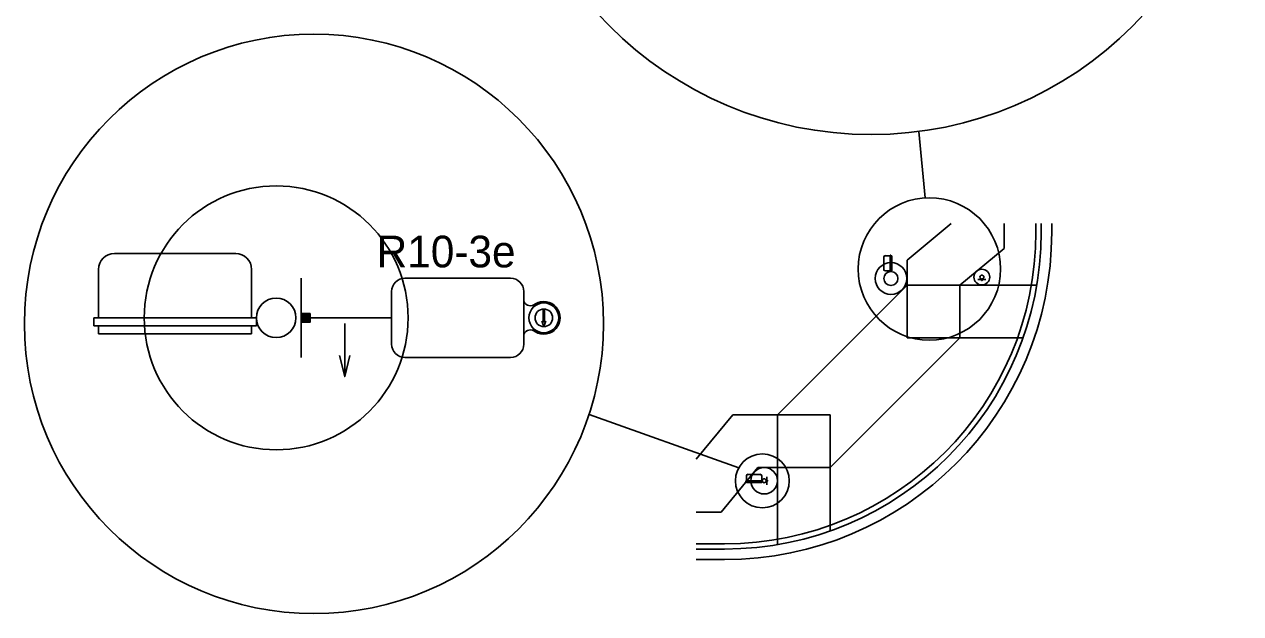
# Model space of a CAD drawing. Extents: x 1369885 to 1370886, y 379976 to 380616.
# Drawn here: x 1370436.8 to 1370609.7, y 380082.1 to 380165.8 of the extents above; entities that cross this region are included whole.
import ezdxf

# ---------------------------------------------------------------- set-up
doc = ezdxf.new("R2010")
doc.units = 0
doc.layers.add('T_Drafting', color=7, linetype='Continuous')

msp = doc.modelspace()

# ---------------------------------------------------------------- linework, layer by layer
at = {"layer": 'T_Drafting'}
for p, q in [((1370564.83, 380141.13), (1370563.93, 380150.57)), ((1370562.24, 380132.29), (1370568.54, 380137.47)), ((1370576.06, 380133.95), (1370576.06, 380137.47)), ((1370580.56, 380136.25), (1370580.56, 380137.47)), ((1370581.31, 380136.25), (1370581.31, 380137.47)), ((1370582.81, 380136.25), (1370582.81, 380137.47)), ((1370449.58, 380133.22), (1370466.83, 380133.22)), ((1370558.93, 380130.97), (1370558.93, 380132.7)), ((1370559.85, 380132.92), (1370559.16, 380132.92)), ((1370559.85, 380130.68), (1370559.85, 380132.99)), ((1370559.96, 380132.99), (1370559.85, 380132.99)), ((1370559.96, 380130.68), (1370559.96, 380132.99)), ((1370560.07, 380132.92), (1370559.96, 380132.92)), ((1370560.07, 380130.75), (1370560.07, 380132.92)), ((1370569.74, 380128.75), (1370576.06, 380133.95)), ((1370447.33, 380124.09), (1370447.33, 380130.97)), ((1370469.08, 380124.09), (1370469.08, 380130.97)), ((1370559.85, 380130.75), (1370559.16, 380130.75)), ((1370559.96, 380130.68), (1370559.85, 380130.68)), ((1370560.07, 380130.75), (1370559.96, 380130.75)), ((1370562.24, 380132.29), (1370562.24, 380121.25)), ((1370476.14, 380129.72), (1370476.14, 380118.47)), ((1370505.89, 380129.72), (1370490.87, 380129.72)), ((1370573.44, 380129.52), (1370572.32, 380129.52)), ((1370572.82, 380129.39), (1370572.82, 380129.52)), ((1370572.82, 380129.39), (1370572.94, 380129.52)), ((1370572.82, 380129.39), (1370572.94, 380129.52)), ((1370572.82, 380129.4), (1370572.94, 380129.52)), ((1370572.82, 380129.4), (1370572.94, 380129.52)), ((1370572.82, 380129.4), (1370572.94, 380129.52)), ((1370572.82, 380129.4), (1370572.94, 380129.52)), ((1370572.82, 380129.4), (1370572.94, 380129.52)), ((1370572.82, 380129.41), (1370572.93, 380129.52)), ((1370572.82, 380129.41), (1370572.93, 380129.52)), ((1370572.82, 380129.41), (1370572.93, 380129.52)), ((1370572.82, 380129.41), (1370572.93, 380129.52)), ((1370572.82, 380129.41), (1370572.92, 380129.52)), ((1370572.82, 380129.42), (1370572.92, 380129.52)), ((1370572.82, 380129.42), (1370572.92, 380129.52)), ((1370572.82, 380129.42), (1370572.92, 380129.52)), ((1370572.82, 380129.42), (1370572.92, 380129.52)), ((1370572.82, 380129.43), (1370572.91, 380129.52)), ((1370572.82, 380129.43), (1370572.91, 380129.52)), ((1370572.82, 380129.43), (1370572.91, 380129.52)), ((1370572.82, 380129.43), (1370572.91, 380129.52)), ((1370572.82, 380129.43), (1370572.91, 380129.52)), ((1370572.82, 380129.44), (1370572.9, 380129.52)), ((1370572.82, 380129.44), (1370572.9, 380129.52)), ((1370572.82, 380129.44), (1370572.9, 380129.52)), ((1370572.82, 380129.44), (1370572.9, 380129.52)), ((1370572.82, 380129.44), (1370572.89, 380129.52)), ((1370572.82, 380129.45), (1370572.89, 380129.52)), ((1370572.82, 380129.45), (1370572.89, 380129.52)), ((1370572.82, 380129.45), (1370572.89, 380129.52)), ((1370572.82, 380129.45), (1370572.89, 380129.52)), ((1370572.82, 380129.45), (1370572.88, 380129.52)), ((1370572.82, 380129.46), (1370572.88, 380129.52)), ((1370572.82, 380129.46), (1370572.88, 380129.52)), ((1370572.82, 380129.46), (1370572.88, 380129.52)), ((1370572.82, 380129.46), (1370572.88, 380129.52)), ((1370572.82, 380129.47), (1370572.87, 380129.52)), ((1370572.82, 380129.47), (1370572.87, 380129.52)), ((1370572.82, 380129.47), (1370572.87, 380129.52)), ((1370572.82, 380129.47), (1370572.87, 380129.52)), ((1370572.82, 380129.47), (1370572.87, 380129.52)), ((1370572.82, 380129.48), (1370572.86, 380129.52)), ((1370572.82, 380129.48), (1370572.86, 380129.52)), ((1370572.82, 380129.48), (1370572.86, 380129.52)), ((1370572.82, 380129.48), (1370572.86, 380129.52)), ((1370572.82, 380129.48), (1370572.85, 380129.52)), ((1370572.82, 380129.49), (1370572.85, 380129.52)), ((1370572.82, 380129.49), (1370572.85, 380129.52)), ((1370572.82, 380129.49), (1370572.85, 380129.52)), ((1370572.82, 380129.49), (1370572.85, 380129.52)), ((1370572.82, 380129.5), (1370572.84, 380129.52)), ((1370572.82, 380129.5), (1370572.84, 380129.52)), ((1370572.82, 380129.5), (1370572.84, 380129.52)), ((1370572.82, 380129.5), (1370572.84, 380129.52)), ((1370572.82, 380129.5), (1370572.84, 380129.52)), ((1370572.82, 380129.51), (1370572.83, 380129.52)), ((1370572.82, 380129.51), (1370572.83, 380129.52)), ((1370572.82, 380129.51), (1370572.83, 380129.52)), ((1370572.82, 380129.51), (1370572.83, 380129.52)), ((1370572.82, 380129.51), (1370572.82, 380129.52)), ((1370572.82, 380129.52), (1370572.82, 380129.52)), ((1370572.82, 380129.52), (1370572.82, 380129.52)), ((1370572.82, 380129.39), (1370572.94, 380129.39)), ((1370572.83, 380129.39), (1370572.94, 380129.51)), ((1370572.83, 380129.39), (1370572.94, 380129.51)), ((1370572.83, 380129.39), (1370572.94, 380129.51)), ((1370572.83, 380129.39), (1370572.94, 380129.51)), ((1370572.83, 380129.39), (1370572.94, 380129.51)), ((1370572.84, 380129.39), (1370572.94, 380129.5)), ((1370572.84, 380129.39), (1370572.94, 380129.5)), ((1370572.84, 380129.39), (1370572.94, 380129.5)), ((1370572.84, 380129.39), (1370572.94, 380129.5)), ((1370572.84, 380129.39), (1370572.94, 380129.5)), ((1370572.85, 380129.39), (1370572.94, 380129.49)), ((1370572.85, 380129.39), (1370572.94, 380129.49)), ((1370572.85, 380129.39), (1370572.94, 380129.49)), ((1370572.85, 380129.39), (1370572.94, 380129.49)), ((1370572.85, 380129.39), (1370572.94, 380129.48)), ((1370572.86, 380129.39), (1370572.94, 380129.48)), ((1370572.86, 380129.39), (1370572.94, 380129.48)), ((1370572.86, 380129.39), (1370572.94, 380129.48)), ((1370572.86, 380129.39), (1370572.94, 380129.48)), ((1370572.87, 380129.39), (1370572.94, 380129.47)), ((1370572.87, 380129.39), (1370572.94, 380129.47)), ((1370572.87, 380129.39), (1370572.94, 380129.47)), ((1370572.87, 380129.39), (1370572.94, 380129.47)), ((1370572.87, 380129.39), (1370572.94, 380129.47)), ((1370572.88, 380129.39), (1370572.94, 380129.46)), ((1370572.88, 380129.39), (1370572.94, 380129.46)), ((1370572.88, 380129.39), (1370572.94, 380129.46)), ((1370572.88, 380129.39), (1370572.94, 380129.46)), ((1370572.88, 380129.39), (1370572.94, 380129.45)), ((1370572.89, 380129.39), (1370572.94, 380129.45)), ((1370572.89, 380129.39), (1370572.94, 380129.45)), ((1370572.89, 380129.39), (1370572.94, 380129.45)), ((1370572.89, 380129.39), (1370572.94, 380129.45)), ((1370572.9, 380129.39), (1370572.94, 380129.44)), ((1370572.9, 380129.39), (1370572.94, 380129.44)), ((1370572.9, 380129.39), (1370572.94, 380129.44)), ((1370572.9, 380129.39), (1370572.94, 380129.44)), ((1370572.9, 380129.39), (1370572.94, 380129.44)), ((1370572.91, 380129.39), (1370572.94, 380129.43)), ((1370572.91, 380129.39), (1370572.94, 380129.43)), ((1370572.91, 380129.39), (1370572.94, 380129.43)), ((1370572.91, 380129.39), (1370572.94, 380129.43)), ((1370572.91, 380129.39), (1370572.94, 380129.43)), ((1370572.92, 380129.39), (1370572.94, 380129.42)), ((1370572.92, 380129.39), (1370572.94, 380129.42)), ((1370572.92, 380129.39), (1370572.94, 380129.42)), ((1370572.92, 380129.39), (1370572.94, 380129.42)), ((1370572.92, 380129.39), (1370572.94, 380129.41)), ((1370572.93, 380129.39), (1370572.94, 380129.41)), ((1370572.93, 380129.39), (1370572.94, 380129.41)), ((1370572.93, 380129.39), (1370572.94, 380129.41)), ((1370572.93, 380129.39), (1370572.94, 380129.41)), ((1370572.94, 380129.39), (1370572.94, 380129.52)), ((1370572.94, 380129.39), (1370572.94, 380129.4)), ((1370572.94, 380129.39), (1370572.94, 380129.4)), ((1370572.94, 380129.39), (1370572.94, 380129.4)), ((1370572.94, 380129.39), (1370572.94, 380129.4)), ((1370572.94, 380129.39), (1370572.94, 380129.4)), ((1370488.99, 380127.84), (1370488.99, 380120.34)), ((1370507.77, 380120.34), (1370507.77, 380127.84)), ((1370562.24, 380128.75), (1370543.81, 380110.32)), ((1370562.24, 380128.75), (1370580.69, 380128.75)), ((1370569.74, 380128.75), (1370569.74, 380121.25)), ((1370446.64, 380124.09), (1370469.77, 380124.09)), ((1370446.64, 380122.97), (1370446.64, 380124.09)), ((1370469.77, 380122.97), (1370469.77, 380124.09)), ((1370477.39, 380124.72), (1370476.14, 380124.72)), ((1370476.14, 380123.47), (1370477.39, 380124.72)), ((1370476.14, 380123.49), (1370477.36, 380124.72)), ((1370476.14, 380123.52), (1370477.34, 380124.72)), ((1370476.14, 380123.54), (1370477.32, 380124.72)), ((1370476.14, 380123.56), (1370477.3, 380124.72)), ((1370476.14, 380123.58), (1370477.28, 380124.72)), ((1370476.14, 380123.6), (1370477.26, 380124.72)), ((1370476.14, 380123.62), (1370477.24, 380124.72)), ((1370476.14, 380123.64), (1370477.22, 380124.72)), ((1370476.14, 380123.66), (1370477.2, 380124.72)), ((1370476.14, 380123.69), (1370477.17, 380124.72)), ((1370476.14, 380123.71), (1370477.15, 380124.72)), ((1370476.14, 380123.73), (1370477.13, 380124.72)), ((1370476.14, 380123.75), (1370477.11, 380124.72)), ((1370476.14, 380123.77), (1370477.09, 380124.72)), ((1370476.14, 380123.79), (1370477.07, 380124.72)), ((1370476.14, 380123.81), (1370477.05, 380124.72)), ((1370476.14, 380123.83), (1370477.03, 380124.72)), ((1370476.14, 380123.86), (1370477, 380124.72)), ((1370476.14, 380123.88), (1370476.98, 380124.72)), ((1370476.14, 380123.9), (1370476.96, 380124.72)), ((1370476.14, 380123.92), (1370476.94, 380124.72)), ((1370476.14, 380123.94), (1370476.92, 380124.72)), ((1370476.14, 380123.96), (1370476.9, 380124.72)), ((1370476.14, 380123.98), (1370476.88, 380124.72)), ((1370476.14, 380124), (1370476.86, 380124.72)), ((1370476.14, 380124.02), (1370476.83, 380124.72)), ((1370476.14, 380124.05), (1370476.81, 380124.72)), ((1370476.14, 380124.07), (1370476.79, 380124.72)), ((1370476.14, 380124.09), (1370476.77, 380124.72)), ((1370476.14, 380124.11), (1370476.75, 380124.72)), ((1370476.14, 380124.13), (1370476.73, 380124.72)), ((1370476.14, 380124.15), (1370476.71, 380124.72)), ((1370476.14, 380124.17), (1370476.69, 380124.72)), ((1370476.14, 380124.19), (1370476.66, 380124.72)), ((1370476.14, 380124.22), (1370476.64, 380124.72)), ((1370476.14, 380124.24), (1370476.62, 380124.72)), ((1370476.14, 380124.26), (1370476.6, 380124.72)), ((1370476.14, 380124.28), (1370476.58, 380124.72)), ((1370476.14, 380124.3), (1370476.56, 380124.72)), ((1370476.14, 380124.32), (1370476.54, 380124.72)), ((1370476.14, 380124.34), (1370476.52, 380124.72)), ((1370476.14, 380124.36), (1370476.5, 380124.72)), ((1370476.14, 380124.39), (1370476.47, 380124.72)), ((1370476.14, 380124.41), (1370476.45, 380124.72)), ((1370476.14, 380124.43), (1370476.43, 380124.72)), ((1370476.14, 380124.45), (1370476.41, 380124.72)), ((1370476.14, 380124.47), (1370476.39, 380124.72)), ((1370476.14, 380124.49), (1370476.37, 380124.72)), ((1370476.14, 380124.51), (1370476.35, 380124.72)), ((1370476.14, 380124.53), (1370476.33, 380124.72)), ((1370476.14, 380124.56), (1370476.3, 380124.72)), ((1370476.14, 380124.58), (1370476.28, 380124.72)), ((1370476.14, 380124.6), (1370476.26, 380124.72)), ((1370476.14, 380124.62), (1370476.24, 380124.72)), ((1370476.14, 380124.64), (1370476.22, 380124.72)), ((1370476.14, 380124.66), (1370476.2, 380124.72)), ((1370476.14, 380124.68), (1370476.18, 380124.72)), ((1370476.14, 380124.7), (1370476.16, 380124.72)), ((1370476.16, 380123.47), (1370477.39, 380124.7)), ((1370476.18, 380123.47), (1370477.39, 380124.68)), ((1370476.2, 380123.47), (1370477.39, 380124.66)), ((1370476.22, 380123.47), (1370477.39, 380124.64)), ((1370476.24, 380123.47), (1370477.39, 380124.62)), ((1370476.26, 380123.47), (1370477.39, 380124.6)), ((1370476.28, 380123.47), (1370477.39, 380124.57)), ((1370476.31, 380123.47), (1370477.39, 380124.55)), ((1370476.33, 380123.47), (1370477.39, 380124.53)), ((1370476.35, 380123.47), (1370477.39, 380124.51)), ((1370476.37, 380123.47), (1370477.39, 380124.49)), ((1370476.39, 380123.47), (1370477.39, 380124.47)), ((1370476.41, 380123.47), (1370477.39, 380124.45)), ((1370476.43, 380123.47), (1370477.39, 380124.43)), ((1370476.45, 380123.47), (1370477.39, 380124.41)), ((1370476.48, 380123.47), (1370477.39, 380124.38)), ((1370476.5, 380123.47), (1370477.39, 380124.36)), ((1370476.52, 380123.47), (1370477.39, 380124.34)), ((1370476.54, 380123.47), (1370477.39, 380124.32)), ((1370476.56, 380123.47), (1370477.39, 380124.3)), ((1370476.58, 380123.47), (1370477.39, 380124.28)), ((1370476.6, 380123.47), (1370477.39, 380124.26)), ((1370476.62, 380123.47), (1370477.39, 380124.24)), ((1370476.65, 380123.47), (1370477.39, 380124.21)), ((1370476.67, 380123.47), (1370477.39, 380124.19)), ((1370476.69, 380123.47), (1370477.39, 380124.17)), ((1370476.71, 380123.47), (1370477.39, 380124.15)), ((1370476.73, 380123.47), (1370477.39, 380124.13)), ((1370476.75, 380123.47), (1370477.39, 380124.11)), ((1370476.77, 380123.47), (1370477.39, 380124.09)), ((1370476.79, 380123.47), (1370477.39, 380124.07)), ((1370476.81, 380123.47), (1370477.39, 380124.04)), ((1370476.84, 380123.47), (1370477.39, 380124.02)), ((1370476.86, 380123.47), (1370477.39, 380124)), ((1370476.88, 380123.47), (1370477.39, 380123.98)), ((1370476.9, 380123.47), (1370477.39, 380123.96)), ((1370476.92, 380123.47), (1370477.39, 380123.94)), ((1370476.94, 380123.47), (1370477.39, 380123.92)), ((1370476.96, 380123.47), (1370477.39, 380123.9)), ((1370476.98, 380123.47), (1370477.39, 380123.87)), ((1370477.01, 380123.47), (1370477.39, 380123.85)), ((1370477.03, 380123.47), (1370477.39, 380123.83)), ((1370477.05, 380123.47), (1370477.39, 380123.81)), ((1370477.07, 380123.47), (1370477.39, 380123.79)), ((1370477.09, 380123.47), (1370477.39, 380123.77)), ((1370477.11, 380123.47), (1370477.39, 380123.75)), ((1370477.13, 380123.47), (1370477.39, 380123.73)), ((1370477.15, 380123.47), (1370477.39, 380123.7)), ((1370477.39, 380123.47), (1370477.39, 380124.72)), ((1370477.39, 380124.09), (1370488.99, 380124.09)), ((1370510.51, 380125.33), (1370510.73, 380125.33)), ((1370510.51, 380123.45), (1370510.51, 380125.33)), ((1370510.73, 380123.45), (1370510.73, 380125.33)), ((1370446.64, 380122.97), (1370469.77, 380122.97)), ((1370447.33, 380121.84), (1370447.33, 380122.97)), ((1370469.08, 380121.84), (1370469.08, 380122.97)), ((1370477.39, 380123.47), (1370476.14, 380123.47)), ((1370477.18, 380123.47), (1370477.39, 380123.68)), ((1370477.2, 380123.47), (1370477.39, 380123.66)), ((1370477.22, 380123.47), (1370477.39, 380123.64)), ((1370477.24, 380123.47), (1370477.39, 380123.62)), ((1370477.26, 380123.47), (1370477.39, 380123.6)), ((1370477.28, 380123.47), (1370477.39, 380123.58)), ((1370477.3, 380123.47), (1370477.39, 380123.56)), ((1370477.32, 380123.47), (1370477.39, 380123.54)), ((1370477.35, 380123.47), (1370477.39, 380123.51)), ((1370477.37, 380123.47), (1370477.39, 380123.49)), ((1370477.39, 380123.47), (1370477.39, 380123.47)), ((1370482.31, 380123.29), (1370482.31, 380115.74)), ((1370510.32, 380123.6), (1370510.62, 380122.84)), ((1370510.51, 380123.45), (1370510.32, 380123.6)), ((1370510.92, 380123.6), (1370510.62, 380122.84)), ((1370510.92, 380123.6), (1370510.73, 380123.45)), ((1370447.33, 380121.84), (1370469.08, 380121.84)), ((1370569.74, 380121.25), (1370551.31, 380102.82)), ((1370562.24, 380121.25), (1370578.74, 380121.25)), ((1370490.87, 380118.47), (1370505.89, 380118.47)), ((1370538.33, 380102.78), (1370517.04, 380110.37)), ((1370537.47, 380110.32), (1370532.27, 380104)), ((1370537.47, 380110.32), (1370551.31, 380110.32)), ((1370543.81, 380110.32), (1370543.81, 380091.88)), ((1370551.31, 380110.32), (1370551.31, 380093.82)), ((1370541.02, 380102.82), (1370535.82, 380096.5)), ((1370539.41, 380100.95), (1370539.41, 380101.64)), ((1370539.64, 380101.86), (1370541.36, 380101.86)), ((1370541.02, 380102.82), (1370551.31, 380102.82)), ((1370541.59, 380100.95), (1370541.59, 380101.64)), ((1370542.3, 380101.51), (1370542.3, 380100.39)), ((1370539.35, 380100.95), (1370541.66, 380100.95)), ((1370539.35, 380100.84), (1370539.35, 380100.95)), ((1370539.35, 380100.84), (1370541.66, 380100.84)), ((1370539.41, 380100.72), (1370539.41, 380100.84)), ((1370539.41, 380100.72), (1370541.59, 380100.72)), ((1370541.59, 380100.72), (1370541.59, 380100.84)), ((1370541.66, 380100.84), (1370541.66, 380100.95)), ((1370542.42, 380101.01), (1370542.3, 380101.01)), ((1370542.3, 380100.89), (1370542.42, 380101.01)), ((1370542.3, 380100.89), (1370542.42, 380101.01)), ((1370542.3, 380100.89), (1370542.42, 380101.01)), ((1370542.3, 380100.89), (1370542.42, 380101.01)), ((1370542.3, 380100.89), (1370542.42, 380101.01)), ((1370542.3, 380100.89), (1370542.42, 380101.01)), ((1370542.3, 380100.89), (1370542.41, 380101.01)), ((1370542.3, 380100.9), (1370542.41, 380101.01)), ((1370542.3, 380100.9), (1370542.41, 380101.01)), ((1370542.3, 380100.9), (1370542.41, 380101.01)), ((1370542.3, 380100.9), (1370542.41, 380101.01)), ((1370542.3, 380100.9), (1370542.4, 380101.01)), ((1370542.3, 380100.91), (1370542.4, 380101.01)), ((1370542.3, 380100.91), (1370542.4, 380101.01)), ((1370542.3, 380100.91), (1370542.4, 380101.01)), ((1370542.3, 380100.91), (1370542.4, 380101.01)), ((1370542.3, 380100.92), (1370542.39, 380101.01)), ((1370542.3, 380100.92), (1370542.39, 380101.01)), ((1370542.3, 380100.92), (1370542.39, 380101.01)), ((1370542.3, 380100.92), (1370542.39, 380101.01)), ((1370542.3, 380100.92), (1370542.38, 380101.01)), ((1370542.3, 380100.93), (1370542.38, 380101.01)), ((1370542.3, 380100.93), (1370542.38, 380101.01)), ((1370542.3, 380100.93), (1370542.38, 380101.01)), ((1370542.3, 380100.93), (1370542.38, 380101.01)), ((1370542.3, 380100.93), (1370542.37, 380101.01)), ((1370542.3, 380100.94), (1370542.37, 380101.01)), ((1370542.3, 380100.94), (1370542.37, 380101.01)), ((1370542.3, 380100.94), (1370542.37, 380101.01)), ((1370542.3, 380100.94), (1370542.37, 380101.01)), ((1370542.3, 380100.94), (1370542.36, 380101.01)), ((1370542.3, 380100.95), (1370542.36, 380101.01)), ((1370542.3, 380100.95), (1370542.36, 380101.01)), ((1370542.3, 380100.95), (1370542.36, 380101.01)), ((1370542.3, 380100.95), (1370542.35, 380101.01)), ((1370542.3, 380100.96), (1370542.35, 380101.01)), ((1370542.3, 380100.96), (1370542.35, 380101.01)), ((1370542.3, 380100.96), (1370542.35, 380101.01)), ((1370542.3, 380100.96), (1370542.35, 380101.01)), ((1370542.3, 380100.96), (1370542.34, 380101.01)), ((1370542.3, 380100.97), (1370542.34, 380101.01)), ((1370542.3, 380100.97), (1370542.34, 380101.01)), ((1370542.3, 380100.97), (1370542.34, 380101.01)), ((1370542.3, 380100.97), (1370542.34, 380101.01)), ((1370542.3, 380100.97), (1370542.33, 380101.01)), ((1370542.3, 380100.98), (1370542.33, 380101.01)), ((1370542.3, 380100.98), (1370542.33, 380101.01)), ((1370542.3, 380100.98), (1370542.33, 380101.01)), ((1370542.3, 380100.98), (1370542.33, 380101.01)), ((1370542.3, 380100.99), (1370542.32, 380101.01)), ((1370542.3, 380100.99), (1370542.32, 380101.01)), ((1370542.3, 380100.99), (1370542.32, 380101.01)), ((1370542.3, 380100.99), (1370542.32, 380101.01)), ((1370542.3, 380100.99), (1370542.31, 380101.01)), ((1370542.3, 380101), (1370542.31, 380101.01)), ((1370542.3, 380101), (1370542.31, 380101.01)), ((1370542.3, 380101), (1370542.31, 380101.01)), ((1370542.3, 380101), (1370542.31, 380101.01)), ((1370542.3, 380101), (1370542.3, 380101.01)), ((1370542.3, 380101.01), (1370542.3, 380101.01)), ((1370542.3, 380101.01), (1370542.3, 380101.01)), ((1370542.3, 380101.01), (1370542.3, 380101.01)), ((1370542.3, 380100.89), (1370542.42, 380101)), ((1370542.42, 380100.89), (1370542.3, 380100.89)), ((1370542.31, 380100.89), (1370542.42, 380101)), ((1370542.31, 380100.89), (1370542.42, 380101)), ((1370542.31, 380100.89), (1370542.42, 380101)), ((1370542.31, 380100.89), (1370542.42, 380101)), ((1370542.31, 380100.89), (1370542.42, 380100.99)), ((1370542.32, 380100.89), (1370542.42, 380100.99)), ((1370542.32, 380100.89), (1370542.42, 380100.99)), ((1370542.32, 380100.89), (1370542.42, 380100.99)), ((1370542.32, 380100.89), (1370542.42, 380100.99)), ((1370542.33, 380100.89), (1370542.42, 380100.98)), ((1370542.33, 380100.89), (1370542.42, 380100.98)), ((1370542.33, 380100.89), (1370542.42, 380100.98)), ((1370542.33, 380100.89), (1370542.42, 380100.98)), ((1370542.33, 380100.89), (1370542.42, 380100.97)), ((1370542.34, 380100.89), (1370542.42, 380100.97)), ((1370542.34, 380100.89), (1370542.42, 380100.97)), ((1370542.34, 380100.89), (1370542.42, 380100.97)), ((1370542.34, 380100.89), (1370542.42, 380100.97)), ((1370542.34, 380100.89), (1370542.42, 380100.96)), ((1370542.35, 380100.89), (1370542.42, 380100.96)), ((1370542.35, 380100.89), (1370542.42, 380100.96)), ((1370542.35, 380100.89), (1370542.42, 380100.96)), ((1370542.35, 380100.89), (1370542.42, 380100.96)), ((1370542.36, 380100.89), (1370542.42, 380100.95)), ((1370542.36, 380100.89), (1370542.42, 380100.95)), ((1370542.36, 380100.89), (1370542.42, 380100.95)), ((1370542.36, 380100.89), (1370542.42, 380100.95)), ((1370542.36, 380100.89), (1370542.42, 380100.94)), ((1370542.37, 380100.89), (1370542.42, 380100.94)), ((1370542.37, 380100.89), (1370542.42, 380100.94)), ((1370542.37, 380100.89), (1370542.42, 380100.94)), ((1370542.37, 380100.89), (1370542.42, 380100.94)), ((1370542.37, 380100.89), (1370542.42, 380100.93)), ((1370542.38, 380100.89), (1370542.42, 380100.93)), ((1370542.38, 380100.89), (1370542.42, 380100.93)), ((1370542.38, 380100.89), (1370542.42, 380100.93)), ((1370542.38, 380100.89), (1370542.42, 380100.93)), ((1370542.38, 380100.89), (1370542.42, 380100.92)), ((1370542.39, 380100.89), (1370542.42, 380100.92)), ((1370542.39, 380100.89), (1370542.42, 380100.92)), ((1370542.39, 380100.89), (1370542.42, 380100.92)), ((1370542.39, 380100.89), (1370542.42, 380100.92)), ((1370542.4, 380100.89), (1370542.42, 380100.91)), ((1370542.4, 380100.89), (1370542.42, 380100.91)), ((1370542.4, 380100.89), (1370542.42, 380100.91)), ((1370542.4, 380100.89), (1370542.42, 380100.91)), ((1370542.4, 380100.89), (1370542.42, 380100.9)), ((1370542.41, 380100.89), (1370542.42, 380100.9)), ((1370542.41, 380100.89), (1370542.42, 380100.9)), ((1370542.41, 380100.89), (1370542.42, 380100.9)), ((1370542.41, 380100.89), (1370542.42, 380100.9)), ((1370542.41, 380100.89), (1370542.42, 380100.89)), ((1370542.42, 380100.89), (1370542.42, 380101.01)), ((1370542.42, 380100.89), (1370542.42, 380100.89)), ((1370542.42, 380100.89), (1370542.42, 380100.89)), ((1370542.42, 380100.89), (1370542.42, 380100.89)), ((1370535.82, 380096.5), (1370532.27, 380096.5)), ((1370536.31, 380092), (1370532.27, 380092)), ((1370536.31, 380091.25), (1370532.27, 380091.25)), ((1370536.31, 380089.75), (1370532.27, 380089.75))]:
    msp.add_line(p, q, dxfattribs=at)
msp.add_lwpolyline([(1370483.06, 380118.74), (1370482.31, 380115.74), (1370481.56, 380118.74)], dxfattribs=at)
for centre, radius in [((1370557.13, 380202.67), 52.54), ((1370477.94, 380123.23), 41.16), ((1370472.58, 380124.09), 18.75), ((1370565.42, 380131.03), 10.12), ((1370559.96, 380129.68), 2.25), ((1370559.96, 380129.68), 1), ((1370572.88, 380129.88), 1.12), ((1370572.88, 380129.88), 0.285), ((1370472.58, 380124.09), 2.81), ((1370510.62, 380124.09), 2.12), ((1370510.62, 380124.09), 1.25), ((1370541.68, 380100.93), 3.83), ((1370541.94, 380100.95), 1.88), ((1370541.94, 380100.95), 0.281)]:
    msp.add_circle(centre, radius, dxfattribs=at)
for centre, radius, start, end in [((1370536.31, 380136.25), 45, 270, 0), ((1370536.31, 380136.25), 46.5, 270, 0), ((1370536.31, 380136.25), 44.25, 270, 0), ((1370449.58, 380130.97), 2.25, 90, 180), ((1370466.83, 380130.97), 2.25, 360, 90), ((1370559.16, 380132.7), 0.225, 90, 180), ((1370559.16, 380130.97), 0.225, 180, 270), ((1370490.87, 380127.84), 1.88, 90, 180), ((1370505.89, 380127.84), 1.88, 0, 90), ((1370508.72, 380126.85), 1.05, 205.1956, 311.8028), ((1370510.62, 380124.09), 2.31, 238.7402, 121.2598), ((1370510.62, 380124.09), 2.31, 42.5066, 121.2598), ((1370508.72, 380121.33), 1.05, 48.1972, 154.8044), ((1370510.62, 380124.09), 2.31, 238.7402, 317.4934), ((1370490.87, 380120.34), 1.88, 180, 270), ((1370505.89, 380120.34), 1.88, 270, 0), ((1370539.64, 380101.64), 0.225, 90, 180), ((1370541.36, 380101.64), 0.225, 360, 90)]:
    msp.add_arc(centre, radius, start, end, dxfattribs=at)

# ---------------------------------------------------------------- texts
msp.add_text('R10-3e', height=4.5, dxfattribs=at).set_placement((1370486.86, 380131.26))

doc.saveas('drawing.dxf')
